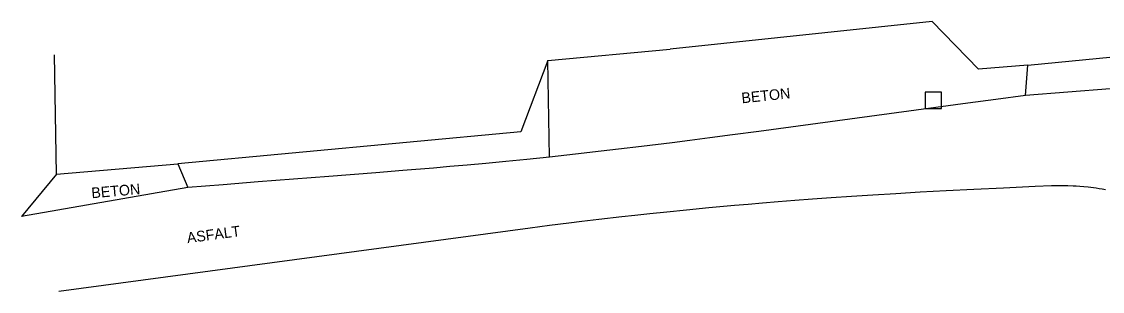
# Model space of a CAD drawing. Extents: x -541281 to -539153, y -1183881 to -1182141.
# Drawn here: x -540121.9 to -540055.8, y -1183218.9 to -1183202.4 of the extents above; entities that cross this region are included whole.
import ezdxf

# ---------------------------------------------------------------- set-up
doc = ezdxf.new("R2010")
doc.units = 0
for name, color, linetype in [('Vrstva 10', 7, 'Continuous'), ('Vrstva 11', 7, 'Continuous'), ('Vrstva 26', 7, 'Continuous'), ('Vrstva 40', 7, 'Continuous'), ('Vrstva 7', 7, 'Continuous'), ('Vrstva 8', 7, 'Continuous')]:
    doc.layers.add(name, color=color, linetype=linetype)

msp = doc.modelspace()

# ---------------------------------------------------------------- linework, layer by layer
at = {"layer": 'Vrstva 10'}
for p, q in [((-540064.013, -1183207.404), (-540076.792, -1183209.137)), ((-540095.68, -1183211.286), (-540096.681, -1183211.372)), ((-540103.075, -1183211.886), (-540107.389, -1183212.22)), ((-540111.7, -1183212.57), (-540121.86, -1183214.34)), ((-540073.511, -1183213.283), (-540074.592, -1183213.365)), ((-540084.369, -1183214.273), (-540085.169, -1183214.362)), ((-540090.76, -1183215.05), (-540105.175, -1183216.985)), ((-540105.175, -1183216.985), (-540119.59, -1183218.92))]:
    msp.add_line(p, q, dxfattribs=at)
for points in [[(-540037.36, -1183204.81), (-540052.71, -1183206.32), (-540060.49, -1183206.94)], [(-540060.49, -1183206.94), (-540062.308, -1183207.177), (-540064.013, -1183207.404)], [(-540076.792, -1183209.137), (-540078.39, -1183209.348), (-540079.789, -1183209.53), (-540081.013, -1183209.687), (-540082.084, -1183209.823), (-540083.959, -1183210.055), (-540085.366, -1183210.223), (-540086.422, -1183210.347)], [(-540086.422, -1183210.347), (-540088.005, -1183210.527), (-540089.59, -1183210.7), (-540090.969, -1183210.844), (-540092.263, -1183210.972), (-540093.476, -1183211.087), (-540094.613, -1183211.192), (-540095.68, -1183211.286)], [(-540096.681, -1183211.372), (-540098.558, -1183211.529), (-540100.2, -1183211.661), (-540103.075, -1183211.886)], [(-540107.389, -1183212.22), (-540109.545, -1183212.392), (-540111.7, -1183212.57)], [(-540063.634, -1183212.679), (-540065.331, -1183212.766), (-540066.923, -1183212.853), (-540068.416, -1183212.941), (-540069.815, -1183213.028), (-540071.128, -1183213.114), (-540072.358, -1183213.2), (-540073.511, -1183213.283)], [(-540055.586, -1183212.707), (-540055.789, -1183212.67), (-540055.98, -1183212.637), (-540056.159, -1183212.609), (-540056.327, -1183212.586), (-540056.644, -1183212.546), (-540056.922, -1183212.518), (-540057.167, -1183212.498), (-540057.381, -1183212.483), (-540057.569, -1183212.473), (-540057.9, -1183212.462), (-540058.149, -1183212.458), (-540058.336, -1183212.458), (-540058.617, -1183212.461), (-540058.9, -1183212.47), (-540059.895, -1183212.51), (-540061.824, -1183212.594), (-540063.634, -1183212.679)], [(-540074.592, -1183213.365), (-540075.605, -1183213.445), (-540076.555, -1183213.523), (-540077.445, -1183213.598), (-540078.28, -1183213.671), (-540079.844, -1183213.814), (-540081.211, -1183213.945), (-540082.408, -1183214.065), (-540083.454, -1183214.174), (-540084.369, -1183214.273)], [(-540085.169, -1183214.362), (-540086.569, -1183214.523), (-540087.618, -1183214.648), (-540088.404, -1183214.745), (-540089.582, -1183214.895), (-540090.76, -1183215.05)]]:
    msp.add_lwpolyline(points, dxfattribs=at)
at = {"layer": 'Vrstva 11'}
for p, q in [((-540089.59, -1183210.7), (-540089.69, -1183204.8)), ((-540060.49, -1183206.94), (-540060.35, -1183205.07)), ((-540112.31, -1183211.11), (-540111.7, -1183212.57)), ((-540119.72, -1183211.75), (-540121.86, -1183214.34))]:
    msp.add_line(p, q, dxfattribs=at)
at = {"layer": 'Vrstva 26'}
msp.add_lwpolyline([(-540066.62, -1183207.72), (-540065.62, -1183207.72), (-540065.62, -1183206.72), (-540066.62, -1183206.72)], close=True, dxfattribs=at)
at = {"layer": 'Vrstva 7'}
for p, q in [((-540066.19, -1183202.41), (-540082.21, -1183204.1)), ((-540119.72, -1183211.75), (-540119.853, -1183204.442)), ((-540089.69, -1183204.8), (-540091.34, -1183209.15)), ((-540091.34, -1183209.15), (-540112.31, -1183211.11))]:
    msp.add_line(p, q, dxfattribs=at)
msp.add_lwpolyline([(-540060.35, -1183205.07), (-540063.35, -1183205.33), (-540066.19, -1183202.41)], dxfattribs=at)
at = {"layer": 'Vrstva 8'}
for p, q in [((-540089.69, -1183204.8), (-540082.21, -1183204.1)), ((-540060.35, -1183205.07), (-540053.01, -1183204.35)), ((-540119.72, -1183211.75), (-540112.31, -1183211.11))]:
    msp.add_line(p, q, dxfattribs=at)

# ---------------------------------------------------------------- texts
at = {"layer": 'Vrstva 40'}
for s, rotation, p in [('BETON', 6.02204, (-540077.815, -1183207.414)), ('BETON', 4.93637, (-540117.568, -1183213.222)), ('ASFALT', 7.64541, (-540111.714, -1183215.972))]:
    msp.add_text(s, height=0.65, rotation=rotation, dxfattribs=at).set_placement(p)

doc.saveas('drawing.dxf')
